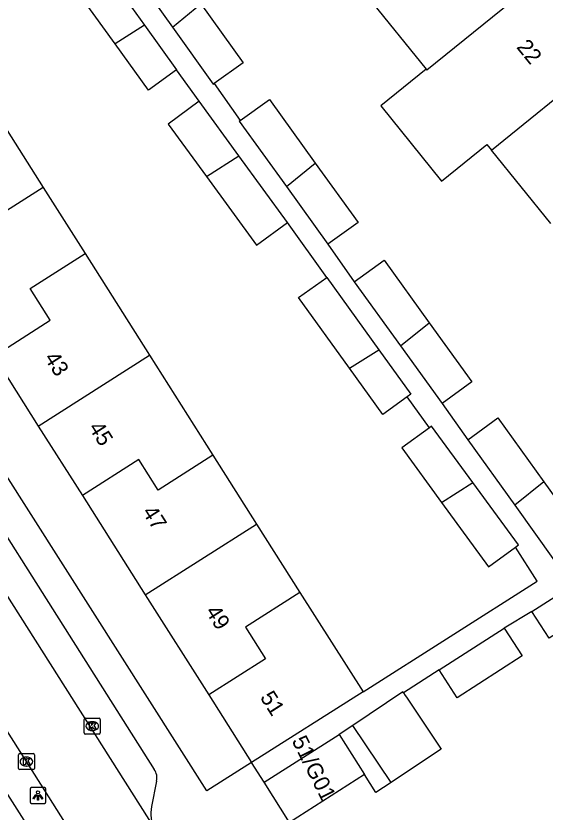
# Model space of a CAD drawing. Extents: x 162347 to 162868, y 381221 to 381813.
# Drawn here: x 162519 to 162552.4, y 381573.3 to 381623.5 of the extents above; entities that cross this region are included whole.
import ezdxf

# ---------------------------------------------------------------- set-up
doc = ezdxf.new("R2010")
doc.units = 0
for name, color, linetype in [('IMGEO_Kolk', 7, 'Continuous'), ('IMGEO_Lichtpunt', 7, 'Continuous'), ('IMGEO_Pand', 7, 'Continuous'), ('IMGEO_Pand_nummerreeks', 7, 'Continuous'), ('IMGEO_Rijbaan_lokaal_open', 7, 'Continuous'), ('IMGEO_Voetpad_open', 7, 'Continuous')]:
    doc.layers.add(name, color=color, linetype=linetype)

msp = doc.modelspace()

# ---------------------------------------------------------------- linework, layer by layer
at = {"layer": 'IMGEO_Kolk'}
for p, q in [((162523.327, 381578.314), (162523.327, 381579.166)), ((162523.402, 381579.24), (162524.254, 381579.24)), ((162524.328, 381579.166), (162524.328, 381578.314)), ((162523.815, 381579.02), (162523.84, 381579.02)), ((162524.254, 381578.24), (162523.402, 381578.24)), ((162523.838, 381578.46), (162523.813, 381578.46)), ((162519.182, 381576.08), (162519.182, 381576.932)), ((162519.257, 381577.006), (162520.109, 381577.006)), ((162519.67, 381576.786), (162519.695, 381576.786)), ((162520.183, 381576.932), (162520.183, 381576.08)), ((162519.693, 381576.226), (162519.668, 381576.226)), ((162520.109, 381576.006), (162519.257, 381576.006))]:
    msp.add_line(p, q, dxfattribs=at)
for points in [[(162523.327, 381578.314), (162523.327, 381579.166)], [(162523.402, 381579.24), (162524.254, 381579.24)], [(162524.328, 381579.166), (162524.328, 381578.314)], [(162523.648, 381578.94), (162523.771, 381578.94), (162523.771, 381578.789), (162523.901, 381578.94), (162524.065, 381578.94), (162523.919, 381578.789), (162524.072, 381578.54), (162523.92, 381578.54), (162523.835, 381578.704), (162523.771, 381578.637), (162523.771, 381578.54), (162523.648, 381578.54), (162523.648, 381578.94)], [(162524.254, 381578.24), (162523.402, 381578.24)], [(162519.182, 381576.08), (162519.182, 381576.932)], [(162519.257, 381577.006), (162520.109, 381577.006)], [(162519.503, 381576.706), (162519.626, 381576.706), (162519.626, 381576.555), (162519.756, 381576.706), (162519.92, 381576.706), (162519.774, 381576.555), (162519.927, 381576.306), (162519.775, 381576.306), (162519.69, 381576.47), (162519.626, 381576.403), (162519.626, 381576.306), (162519.503, 381576.306), (162519.503, 381576.706)], [(162520.183, 381576.932), (162520.183, 381576.08)], [(162520.109, 381576.006), (162519.257, 381576.006)]]:
    msp.add_lwpolyline(points, dxfattribs=at)
for centre, start, end in [((162523.404, 381579.164), 91.552, 178.448), ((162523.404, 381579.164), 91.552, 178.448), ((162524.252, 381579.164), 1.552, 88.448), ((162524.252, 381579.164), 1.552, 88.448), ((162523.404, 381578.316), 181.552, 268.448), ((162523.404, 381578.316), 181.552, 268.448), ((162524.252, 381578.316), 271.552, 358.448), ((162524.252, 381578.316), 271.552, 358.448), ((162519.259, 381576.93), 91.552, 178.448), ((162519.259, 381576.93), 91.552, 178.448), ((162520.107, 381576.93), 1.552, 88.448), ((162520.107, 381576.93), 1.552, 88.448), ((162519.259, 381576.082), 181.552, 268.448), ((162519.259, 381576.082), 181.552, 268.448), ((162520.107, 381576.082), 271.552, 358.448), ((162520.107, 381576.082), 271.552, 358.448)]:
    msp.add_arc(centre, 0.0765, start, end, dxfattribs=at)
for centre, major_axis, ratio, start_param, end_param in [((162523.814, 381578.74), (-0.387, 0.002), 0.722429, 4.712389, 7.853982), ((162523.839, 381578.74), (-0.39, 0.002), 0.717154, 1.570796, 4.712389), ((162519.669, 381576.506), (-0.387, 0.002), 0.722429, 4.712389, 7.853982), ((162519.694, 381576.506), (-0.39, 0.002), 0.717154, 1.570796, 4.712389)]:
    msp.add_ellipse(centre, major_axis=major_axis, ratio=ratio, start_param=start_param, end_param=end_param, dxfattribs=at)
at = {"layer": 'IMGEO_Lichtpunt'}
for p, q in [((162519.911, 381574.774), (162519.911, 381573.967)), ((162519.911, 381574.774), (162519.911, 381573.967)), ((162520.813, 381574.869), (162520.005, 381574.869)), ((162520.813, 381574.869), (162520.005, 381574.869)), ((162520.907, 381573.967), (162520.907, 381574.774)), ((162520.907, 381573.967), (162520.907, 381574.774)), ((162520.005, 381573.873), (162520.813, 381573.873)), ((162520.005, 381573.873), (162520.813, 381573.873))]:
    msp.add_line(p, q, dxfattribs=at)
for points in [[(162520.285, 381574.438), (162520.324, 381574.41), (162520.136, 381574.148), (162520.098, 381574.175), (162520.285, 381574.438)], [(162520.387, 381574.39), (162520.434, 381574.39), (162520.434, 381574.068), (162520.387, 381574.068), (162520.387, 381574.39)], [(162520.497, 381574.41), (162520.535, 381574.437), (162520.722, 381574.175), (162520.683, 381574.147), (162520.497, 381574.41)]]:
    msp.add_lwpolyline(points, dxfattribs=at)
msp.add_circle((162520.41, 381574.572), 0.0994, dxfattribs=at)
for centre, start, end in [((162520.005, 381574.774), 90, 180), ((162520.005, 381574.774), 90, 180), ((162520.813, 381574.774), 0, 90), ((162520.813, 381574.774), 0, 90), ((162520.005, 381573.967), 180, 270), ((162520.005, 381573.967), 180, 270), ((162520.813, 381573.967), 270, 0), ((162520.813, 381573.967), 270, 360)]:
    msp.add_arc(centre, 0.0946, start, end, dxfattribs=at)
at = {"layer": 'IMGEO_Pand'}
for points in [[(162525.275, 381621.701), (162522.066, 381626.149), (162523.834, 381627.425)], [(162523.834, 381627.425), (162527.117, 381622.873)], [(162526, 381626.917), (162525.943, 381626.876), (162528.879, 381622.762)], [(162551.438, 381625.343), (162544.909, 381620.041), (162544.856, 381620.107)], [(162528.879, 381622.762), (162530.674, 381624.218)], [(162530.674, 381624.218), (162533.328, 381620.5), (162531.501, 381619.196)], [(162541.181, 381624.654), (162544.856, 381620.107)], [(162527.117, 381622.873), (162525.275, 381621.701)], [(162527.117, 381622.873), (162529.142, 381620.065)], [(162528.879, 381622.762), (162531.45, 381619.16), (162531.501, 381619.196)], [(162529.142, 381620.065), (162527.374, 381618.79), (162525.275, 381621.701)], [(162548.983, 381614.999), (162555.512, 381620.301)], [(162544.856, 381620.107), (162542.005, 381617.803), (162545.837, 381613.06), (162548.688, 381615.364), (162548.983, 381614.999)], [(162533.154, 381616.877), (162534.984, 381618.198), (162537.875, 381614.19)], [(162530.562, 381618.083), (162528.606, 381616.655), (162531.014, 381613.356)], [(162533.062, 381614.658), (162530.562, 381618.083)], [(162517.95, 381617.043), (162520.727, 381612.666)], [(162533.154, 381616.877), (162533.084, 381616.827), (162536.054, 381612.711)], [(162552.71, 381610.388), (162548.983, 381614.999)], [(162531.014, 381613.356), (162533.062, 381614.658)], [(162536.135, 381610.447), (162533.062, 381614.658)], [(162536.054, 381612.711), (162537.875, 381614.19)], [(162537.875, 381614.19), (162540.57, 381610.455), (162538.67, 381609.084)], [(162531.014, 381613.356), (162534.179, 381609.019), (162536.135, 381610.447)], [(162520.727, 381612.666), (162513.719, 381608.21)], [(162520.727, 381612.666), (162523.373, 381608.497)], [(162536.054, 381612.711), (162538.67, 381609.084)], [(162517.63, 381602.045), (162521.182, 381604.304), (162519.915, 381606.298), (162523.373, 381608.497)], [(162523.373, 381608.497), (162527.437, 381602.092)], [(162540.325, 381606.725), (162542.212, 381608.087), (162545.056, 381604.145)], [(162540.035, 381601.272), (162536.826, 381605.721), (162538.594, 381606.997)], [(162538.594, 381606.997), (162541.878, 381602.444)], [(162540.325, 381606.725), (162543.247, 381602.676)], [(162543.247, 381602.676), (162545.056, 381604.145)], [(162545.056, 381604.145), (162547.745, 381600.418), (162545.859, 381599.057)], [(162543.247, 381602.676), (162545.859, 381599.057)], [(162540.035, 381601.272), (162541.878, 381602.444)], [(162541.878, 381602.444), (162543.902, 381599.637), (162543.669, 381599.469)], [(162517.63, 381602.045), (162520.428, 381597.636)], [(162520.428, 381597.636), (162527.437, 381602.092)], [(162527.437, 381602.092), (162531.429, 381595.8)], [(162543.669, 381599.469), (162542.134, 381598.362), (162540.035, 381601.272)], [(162547.476, 381596.777), (162549.379, 381598.143), (162552.266, 381594.122)], [(162520.428, 381597.636), (162523.206, 381593.256)], [(162547.795, 381594.084), (162545.203, 381597.632), (162545.066, 381597.532)], [(162545.066, 381597.532), (162543.318, 381596.255), (162545.822, 381592.829)], [(162547.476, 381596.777), (162550.444, 381592.644)], [(162531.429, 381595.8), (162527.983, 381593.608), (162526.767, 381595.521), (162523.206, 381593.256)], [(162531.429, 381595.8), (162534.178, 381591.467)], [(162552.266, 381594.122), (162550.444, 381592.644)], [(162552.266, 381594.122), (162554.849, 381590.523)], [(162545.822, 381592.829), (162547.795, 381594.084)], [(162550.489, 381590.011), (162550.674, 381590.145), (162547.795, 381594.084)], [(162523.206, 381593.256), (162527.169, 381587.01)], [(162545.822, 381592.829), (162548.782, 381588.779), (162550.489, 381590.011)], [(162550.444, 381592.644), (162552.947, 381589.157), (162554.849, 381590.523)], [(162527.169, 381587.01), (162534.178, 381591.467)], [(162534.178, 381591.467), (162536.909, 381587.162)], [(162551.524, 381585.958), (162555.632, 381588.581)], [(162536.909, 381587.162), (162533.473, 381584.977), (162534.74, 381582.983), (162531.166, 381580.71)], [(162536.909, 381587.162), (162540.886, 381580.895)], [(162527.169, 381587.01), (162531.166, 381580.71)], [(162556.907, 381587.02), (162552.601, 381584.271), (162551.524, 381585.958)], [(162549.776, 381584.918), (162550.906, 381583.156), (162546.803, 381580.525), (162545.673, 381582.287)], [(162545.673, 381582.287), (162549.776, 381584.918)], [(162531.166, 381580.71), (162533.863, 381576.458)], [(162540.886, 381580.895), (162533.863, 381576.458)], [(162543.432, 381580.838), (162543.398, 381580.889), (162540.246, 381578.787)], [(162543.432, 381580.838), (162543.544, 381580.67), (162543.621, 381580.554), (162545.799, 381577.287), (162542.929, 381575.374), (162542.647, 381575.186)], [(162540.246, 381578.787), (162539.372, 381578.205)], [(162542.647, 381575.186), (162540.246, 381578.787)], [(162534.661, 381575.207), (162539.372, 381578.205)], [(162539.372, 381578.205), (162540.977, 381575.683)], [(162540.977, 381575.683), (162536.254, 381572.675)], [(162542.647, 381575.186), (162541.696, 381574.552), (162540.977, 381575.683)], [(162536.254, 381572.675), (162534.661, 381575.207)]]:
    msp.add_lwpolyline(points, dxfattribs=at)
at = {"layer": 'IMGEO_Rijbaan_lokaal_open'}
for points in [[(162508.323, 381602.896), (162527.79, 381572.233)], [(162536.173, 381550.404), (162533.548, 381554.605), (162528.482, 381562.594), (162519.683, 381576.506), (162509.771, 381592.107), (162504.221, 381600.859)]]:
    msp.add_lwpolyline(points, dxfattribs=at)
at = {"layer": 'IMGEO_Voetpad_open'}
for points in [[(162533.863, 381576.458), (162531.035, 381574.671), (162500, 381623.471), (162483.717, 381649.074), (162486.625, 381650.919)], [(162482.857, 381630.326), (162500, 381603.428), (162522.094, 381568.761), (162522.773, 381567.696)], [(162530.562, 381618.083), (162529.142, 381620.065)], [(162531.501, 381619.196), (162533.154, 381616.877)], [(162538.594, 381606.997), (162536.135, 381610.447)], [(162538.67, 381609.084), (162540.325, 381606.725)], [(162510.585, 381603.042), (162527.735, 381576.018)], [(162545.066, 381597.532), (162543.669, 381599.469)], [(162545.859, 381599.057), (162547.476, 381596.777)], [(162540.886, 381580.895), (162551.857, 381587.857), (162550.489, 381590.011)], [(162551.524, 381585.958), (162549.776, 381584.918)], [(162545.673, 381582.287), (162543.432, 381580.838)], [(162534.661, 381575.207), (162533.863, 381576.458)], [(162527.883, 381575.272), (162527.569, 381573.684)]]:
    msp.add_lwpolyline(points, dxfattribs=at)
for centre, radius, start, end in [((162526.964, 381575.477), 0.941, 347.399, 35.0436), ((162529.375, 381573.217), 1.865, 165.4943, 211.8258)]:
    msp.add_arc(centre, radius, start, end, dxfattribs=at)

# ---------------------------------------------------------------- texts
at = {"layer": 'IMGEO_Pand_nummerreeks'}
for s, rotation, p in [('22', 309.0755, (162550.508, 381621.484)), ('43', 302.4521, (162520.772, 381601.927)), ('45', 302.4521, (162523.565, 381597.536)), ('47', 302.4464, (162526.941, 381592.227)), ('49', 302.4521, (162530.927, 381585.957)), ('51', 302.4521, (162534.366, 381580.55)), ('51/G01', 296.5678, (162536.373, 381577.828))]:
    msp.add_text(s, height=1, rotation=rotation, dxfattribs=at).set_placement(p)

doc.saveas('drawing.dxf')
